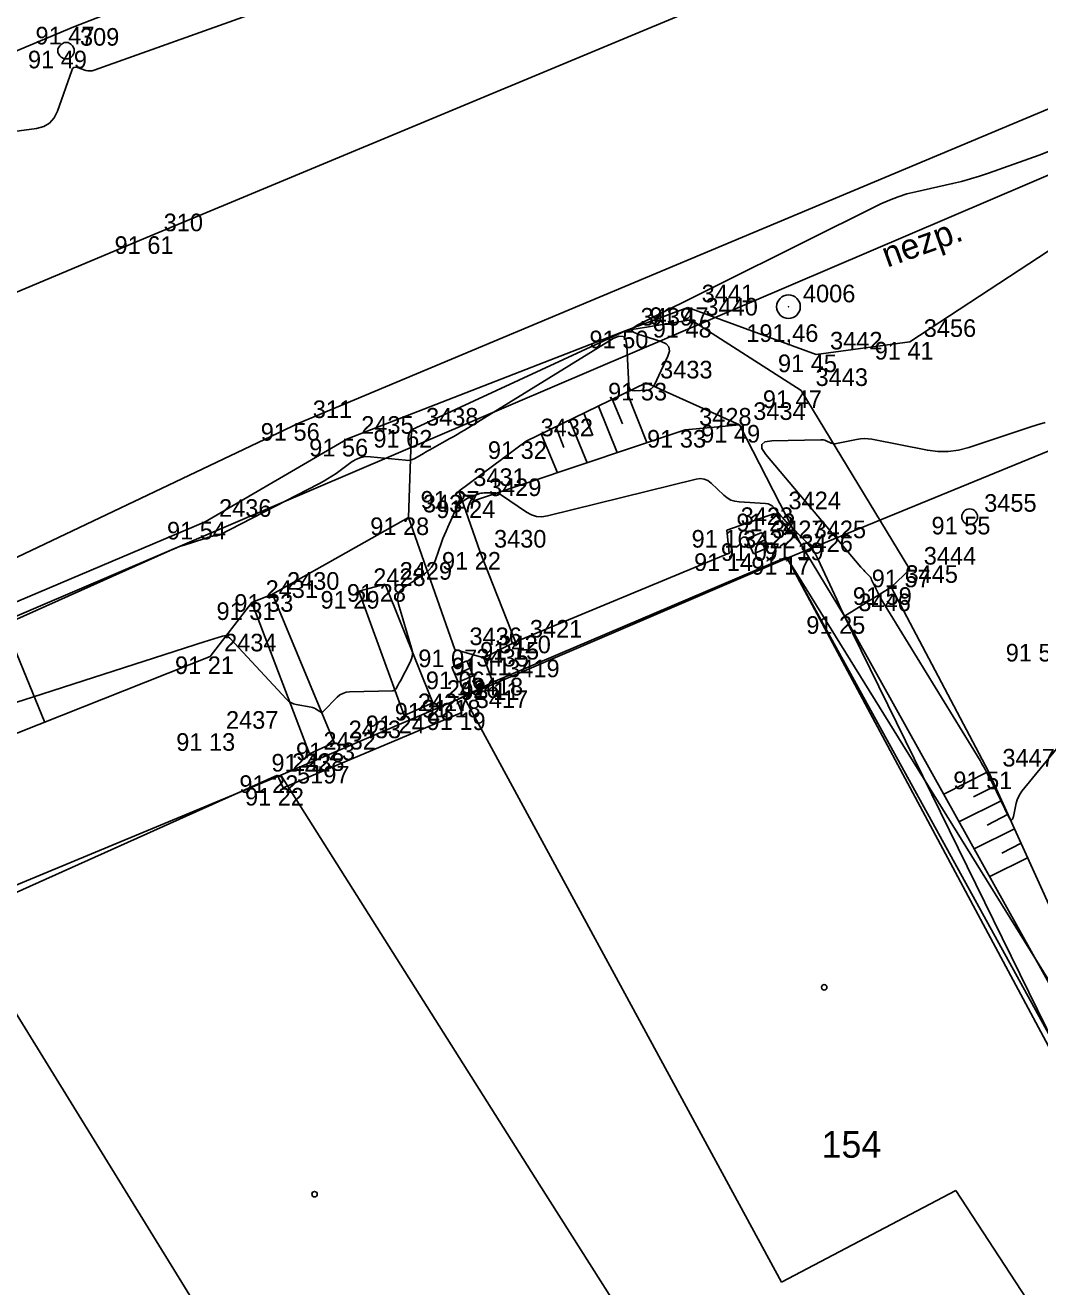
# Model space of a CAD drawing. Extents: x -711081 to -709338, y -1025122 to -1024092.
# Drawn here: x -710543.62 to -710527.5, y -1024855.64 to -1024835.58 of the extents above; entities that cross this region are included whole.
import ezdxf

# ---------------------------------------------------------------- set-up
doc = ezdxf.new("R2010")
doc.units = 0
for name, color, linetype in [('Ex_Minor Contours', 7, 'Continuous'), ('Z_bodove_pole', 7, 'Continuous'), ('Z_bodove_pole_cisla', 7, 'Continuous'), ('Z_bodove_pole_vysky', 7, 'Continuous'), ('Z_body', 7, 'Continuous'), ('Z_body_cisla', 7, 'Continuous'), ('Z_body_vysky_redukovane', 7, 'Continuous'), ('Z_budova', 7, 'Continuous'), ('Z_hrany_paty', 7, 'Continuous'), ('Z_katastr_cisla_stavebni', 7, 'Continuous'), ('Z_katastr_hranice', 7, 'Continuous'), ('Z_katastr_vnitrni_kresba', 7, 'Continuous'), ('Z_katastr_znacky_budov', 7, 'Continuous'), ('Z_komunikace', 7, 'Continuous'), ('Z_komunikace_osa', 7, 'Continuous'), ('Z_patnik_zula', 7, 'Continuous'), ('Z_popisy', 7, 'Continuous'), ('Z_rozhranni', 7, 'Continuous'), ('Z_site_kanalizace_znaky', 7, 'Continuous'), ('Z_site_vodovod_znaky', 7, 'Continuous'), ('Z_srafy_zelen', 7, 'Continuous'), ('Z_technicke_srafy', 7, 'Continuous'), ('Z_vstupy', 7, 'Continuous'), ('Z_zelen_obvod', 7, 'Continuous'), ('Z_zlabek', 7, 'Continuous')]:
    doc.layers.add(name, color=color, linetype=linetype)

# ---------------------------------------------------------------- blocks, each defined once
blk = doc.blocks.new('POINT_DISPLAY')
blk.add_line((0, 0), (0, 0))
blk = doc.blocks.new('Z614')
for p, q in [((-0.13, 0.03), (-0.1, 0.08)), ((-0.13, -0.03), (-0.13, 0.03)), ((-0.1, 0.08), (-0.08, 0.1)), ((-0.08, 0.1), (-0.03, 0.13)), ((-0.03, 0.13), (0.03, 0.13)), ((0.03, 0.13), (0.08, 0.1)), ((0.08, 0.1), (0.1, 0.08)), ((0.1, 0.08), (0.13, 0.03)), ((0.13, 0.03), (0.13, -0.03)), ((-0.1, -0.08), (-0.13, -0.03)), ((-0.08, -0.1), (-0.1, -0.08)), ((-0.03, -0.13), (-0.08, -0.1)), ((0.03, -0.13), (-0.03, -0.13)), ((0.08, -0.1), (0.03, -0.13)), ((0.1, -0.08), (0.08, -0.1)), ((0.13, -0.03), (0.1, -0.08))]:
    blk.add_line(p, q)
blk = doc.blocks.new('Z15')
blk.add_circle((0, 0), 0.125)
blk = doc.blocks.new('Z46260')
for p, q in [((0.13, 0.13), (-0.13, 0.13)), ((-0.13, 0.13), (-0.13, -0.13)), ((0.13, 0), (-0.13, 0)), ((0.13, -0.13), (0.13, 0.13)), ((-0.13, -0.13), (0.13, -0.13))]:
    blk.add_line(p, q)
blk = doc.blocks.new('Z101')
for radius in [0.188, 0.0025]:
    blk.add_circle((0, 0), radius)

msp = doc.modelspace()

# ---------------------------------------------------------------- linework, layer by layer
at = {"layer": 'Ex_Minor Contours'}
for points in [[(-710546.514, -1024837.638), (-710543.441, -1024837.225), (-710543.326, -1024837.195), (-710543.232, -1024837.14), (-710543.159, -1024837.059), (-710543.107, -1024836.953), (-710542.882, -1024836.303), (-710542.868, -1024836.275), (-710542.848, -1024836.258), (-710542.823, -1024836.252), (-710542.792, -1024836.258), (-710542.658, -1024836.302), (-710542.624, -1024836.31), (-710542.591, -1024836.312), (-710542.558, -1024836.309), (-710542.524, -1024836.3), (-710539.776, -1024835.318)], [(-710527.358, -1024837.594), (-710527.506, -1024837.652), (-710528.312, -1024837.938), (-710528.453, -1024837.985), (-710528.595, -1024838.028), (-710528.739, -1024838.067), (-710528.883, -1024838.102), (-710529.464, -1024838.231), (-710529.608, -1024838.267), (-710529.749, -1024838.312), (-710529.887, -1024838.365), (-710530.021, -1024838.427), (-710533.895, -1024840.353), (-710533.96, -1024840.395), (-710533.98, -1024840.433), (-710533.954, -1024840.467), (-710533.883, -1024840.498), (-710533.511, -1024840.613), (-710533.434, -1024840.649), (-710533.391, -1024840.7), (-710533.382, -1024840.766), (-710533.407, -1024840.847), (-710533.618, -1024841.3), (-710533.641, -1024841.336), (-710533.67, -1024841.363), (-710533.706, -1024841.38), (-710533.748, -1024841.388), (-710533.931, -1024841.398), (-710533.972, -1024841.394), (-710534.001, -1024841.379), (-710534.02, -1024841.351), (-710534.027, -1024841.311), (-710534.058, -1024840.681), (-710534.076, -1024840.583), (-710534.118, -1024840.532), (-710534.185, -1024840.526), (-710534.275, -1024840.566), (-710536.637, -1024842.021), (-710536.695, -1024842.056), (-710536.753, -1024842.091), (-710536.811, -1024842.124), (-710536.87, -1024842.157), (-710537.154, -1024842.314), (-710537.188, -1024842.333), (-710537.223, -1024842.353), (-710537.257, -1024842.372), (-710537.292, -1024842.392), (-710537.429, -1024842.471), (-710537.464, -1024842.488), (-710537.5, -1024842.499), (-710537.538, -1024842.504), (-710537.576, -1024842.502), (-710538.133, -1024842.444), (-710538.211, -1024842.443), (-710538.285, -1024842.456), (-710538.355, -1024842.482), (-710538.422, -1024842.522), (-710538.681, -1024842.71), (-710538.746, -1024842.756), (-710538.814, -1024842.799), (-710538.883, -1024842.84), (-710538.953, -1024842.877), (-710540.539, -1024843.69), (-710540.548, -1024843.694), (-710540.557, -1024843.697), (-710540.566, -1024843.699), (-710540.575, -1024843.7), (-710540.613, -1024843.702), (-710540.622, -1024843.702), (-710540.631, -1024843.704), (-710540.64, -1024843.706), (-710540.649, -1024843.708), (-710540.721, -1024843.73), (-710540.75, -1024843.739), (-710540.78, -1024843.749), (-710541.093, -1024843.85), (-710541.15, -1024843.869), (-710541.206, -1024843.889), (-710541.262, -1024843.912), (-710541.317, -1024843.935), (-710548.267, -1024847.049)], [(-710526.884, -1024846.672), (-710527.779, -1024847.761), (-710527.81, -1024847.805), (-710527.836, -1024847.851), (-710527.856, -1024847.9), (-710527.87, -1024847.952), (-710527.916, -1024848.165), (-710527.929, -1024848.206), (-710527.944, -1024848.221), (-710527.964, -1024848.21), (-710527.986, -1024848.174), (-710528.183, -1024847.765), (-710528.203, -1024847.723), (-710528.224, -1024847.682), (-710528.245, -1024847.641), (-710528.267, -1024847.6), (-710528.354, -1024847.437), (-710528.376, -1024847.396), (-710528.399, -1024847.356), (-710528.423, -1024847.316), (-710528.446, -1024847.276), (-710530.015, -1024844.708), (-710530.035, -1024844.675), (-710530.054, -1024844.641), (-710530.072, -1024844.606), (-710530.088, -1024844.571), (-710530.168, -1024844.4), (-710530.178, -1024844.381), (-710530.189, -1024844.362), (-710530.202, -1024844.345), (-710530.217, -1024844.329), (-710530.279, -1024844.267), (-710530.294, -1024844.251), (-710530.309, -1024844.235), (-710530.324, -1024844.218), (-710530.338, -1024844.202), (-710531.852, -1024842.408), (-710531.912, -1024842.315), (-710531.916, -1024842.249), (-710531.864, -1024842.208), (-710531.755, -1024842.192), (-710530.977, -1024842.174), (-710530.955, -1024842.174), (-710530.933, -1024842.177), (-710530.913, -1024842.183), (-710530.892, -1024842.191), (-710530.811, -1024842.227), (-710530.791, -1024842.234), (-710530.77, -1024842.238), (-710530.749, -1024842.239), (-710530.728, -1024842.236), (-710530.407, -1024842.169), (-710530.346, -1024842.159), (-710530.285, -1024842.156), (-710530.224, -1024842.159), (-710530.163, -1024842.168), (-710529.283, -1024842.341), (-710529.117, -1024842.363), (-710528.952, -1024842.364), (-710528.789, -1024842.342), (-710528.626, -1024842.299), (-710527.655, -1024841.975), (-710527.535, -1024841.937), (-710527.413, -1024841.901)], [(-710527.253, -1024851.809), (-710530.471, -1024845.243), (-710530.535, -1024845.111), (-710530.599, -1024844.979), (-710530.661, -1024844.847), (-710530.723, -1024844.714), (-710531.023, -1024844.067), (-710531.061, -1024843.994), (-710531.104, -1024843.925), (-710531.154, -1024843.86), (-710531.209, -1024843.799), (-710531.502, -1024843.503), (-710531.531, -1024843.474), (-710531.559, -1024843.444), (-710531.586, -1024843.413), (-710531.613, -1024843.382), (-710531.719, -1024843.256), (-710531.748, -1024843.228), (-710531.779, -1024843.208), (-710531.815, -1024843.194), (-710531.854, -1024843.188), (-710532.276, -1024843.163), (-710532.343, -1024843.153), (-710532.406, -1024843.133), (-710532.464, -1024843.101), (-710532.516, -1024843.058), (-710532.718, -1024842.865), (-710532.771, -1024842.825), (-710532.828, -1024842.801), (-710532.889, -1024842.793), (-710532.955, -1024842.802), (-710535.322, -1024843.387), (-710535.41, -1024843.4), (-710535.494, -1024843.394), (-710535.575, -1024843.37), (-710535.653, -1024843.327), (-710536.052, -1024843.054), (-710536.081, -1024843.037), (-710536.111, -1024843.026), (-710536.142, -1024843.019), (-710536.175, -1024843.017), (-710536.328, -1024843.021), (-710536.353, -1024843.023), (-710536.377, -1024843.026), (-710536.401, -1024843.032), (-710536.424, -1024843.039), (-710536.517, -1024843.073), (-710536.54, -1024843.082), (-710536.562, -1024843.093), (-710536.584, -1024843.104), (-710536.605, -1024843.117), (-710536.698, -1024843.178), (-710536.719, -1024843.194), (-710536.737, -1024843.212), (-710536.752, -1024843.233), (-710536.765, -1024843.256), (-710536.906, -1024843.566), (-710536.932, -1024843.626), (-710536.957, -1024843.686), (-710536.981, -1024843.747), (-710537.003, -1024843.809), (-710537.099, -1024844.083), (-710537.126, -1024844.145), (-710537.162, -1024844.202), (-710537.207, -1024844.251), (-710537.261, -1024844.294), (-710537.592, -1024844.518), (-710537.654, -1024844.573), (-710537.691, -1024844.636), (-710537.703, -1024844.709), (-710537.689, -1024844.791), (-710537.479, -1024845.486), (-710537.468, -1024845.545), (-710537.467, -1024845.602), (-710537.479, -1024845.658), (-710537.502, -1024845.712), (-710537.658, -1024846.006), (-710537.675, -1024846.037), (-710537.692, -1024846.069), (-710537.727, -1024846.132), (-710537.737, -1024846.146), (-710537.749, -1024846.156), (-710537.763, -1024846.163), (-710537.78, -1024846.165), (-710538.464, -1024846.184), (-710538.52, -1024846.19), (-710538.571, -1024846.207), (-710538.619, -1024846.233), (-710538.662, -1024846.27), (-710538.878, -1024846.49), (-710538.893, -1024846.501), (-710538.907, -1024846.506), (-710538.923, -1024846.504), (-710538.939, -1024846.497), (-710539.005, -1024846.454), (-710539.021, -1024846.444), (-710539.039, -1024846.436), (-710539.057, -1024846.43), (-710539.076, -1024846.426), (-710539.314, -1024846.383), (-710539.359, -1024846.372), (-710539.4, -1024846.354), (-710539.437, -1024846.329), (-710539.47, -1024846.298), (-710540.367, -1024845.329), (-710540.393, -1024845.307), (-710540.421, -1024845.294), (-710540.451, -1024845.291), (-710540.484, -1024845.297), (-710540.621, -1024845.339), (-710540.655, -1024845.35), (-710540.69, -1024845.361), (-710540.724, -1024845.372), (-710540.758, -1024845.383), (-710543.506, -1024846.266), (-710543.754, -1024846.349)]]:
    msp.add_lwpolyline(points, dxfattribs=at)
at = {"layer": 'Z_budova'}
for p, q in [((-710536.19, -1024846.03), (-710531.52, -1024844.04)), ((-710531.52, -1024844.04), (-710526.72, -1024852.78)), ((-710536.76, -1024846.31), (-710536.19, -1024846.03)), ((-710536.68, -1024846.51), (-710536.76, -1024846.31)), ((-710539.61, -1024847.51), (-710544.72, -1024849.8)), ((-710539.52, -1024847.71), (-710539.61, -1024847.51))]:
    msp.add_line(p, q, dxfattribs=at)
at = {"layer": 'Z_hrany_paty'}
for p, q in [((-710533.13, -1024842.02), (-710536.48, -1024843.14)), ((-710533.13, -1024842.02), (-710532.27, -1024841.94)), ((-710536.73, -1024842.99), (-710536.48, -1024843.14)), ((-710539.69, -1024844.63), (-710537.53, -1024843.41)), ((-710529.86, -1024844.52), (-710528.31, -1024847.45)), ((-710540.68, -1024845.62), (-710540.02, -1024844.76)), ((-710540.68, -1024845.62), (-710545.01, -1024847.34)), ((-710528.31, -1024847.45), (-710526.08, -1024852.38))]:
    msp.add_line(p, q, dxfattribs=at)
at = {"layer": 'Z_katastr_hranice'}
for p, q in [((-710562.9, -1024853.16), (-710522.93, -1024836.07)), ((-710531.51, -1024844.06), (-710526.89, -1024842.16)), ((-710531.51, -1024844.06), (-710536.65, -1024846.26)), ((-710521.2, -1024860.71), (-710531.51, -1024844.06)), ((-710536.65, -1024846.26), (-710539.56, -1024847.51)), ((-710539.56, -1024847.51), (-710544.77, -1024849.67)), ((-710539.56, -1024847.51), (-710535.45, -1024854.01)), ((-710535.45, -1024854.01), (-710530.21, -1024862.29))]:
    msp.add_line(p, q, dxfattribs=at)
at = {"layer": 'Z_katastr_vnitrni_kresba'}
for p, q in [((-710526.72, -1024853.01), (-710531.51, -1024844.06)), ((-710536.65, -1024846.26), (-710531.6, -1024855.57)), ((-710544.77, -1024849.67), (-710540.21, -1024857.07)), ((-710531.6, -1024855.57), (-710528.83, -1024854.11)), ((-710528.83, -1024854.11), (-710523.54, -1024862.2))]:
    msp.add_line(p, q, dxfattribs=at)
at = {"layer": 'Z_katastr_znacky_budov'}
for centre in [(-710530.922, -1024850.88), (-710539.022, -1024854.17)]:
    msp.add_circle(centre, 0.0437, dxfattribs=at)
at = {"layer": 'Z_komunikace'}
for p, q in [((-710542.85, -1024835.61), (-710529.22, -1024830.3)), ((-710556.39, -1024841.31), (-710542.85, -1024835.61)), ((-710539.27, -1024841.91), (-710526.42, -1024836.52)), ((-710544.51, -1024844.4), (-710539.27, -1024841.91))]:
    msp.add_line(p, q, dxfattribs=at)
at = {"layer": 'Z_komunikace_osa'}
for p, q in [((-710541.64, -1024838.94), (-710528.14, -1024833.31)), ((-710555.08, -1024844.58), (-710541.64, -1024838.94))]:
    msp.add_line(p, q, dxfattribs=at)
at = {"layer": 'Z_rozhranni'}
for p, q in [((-710529.56, -1024840.62), (-710525.29, -1024837.81)), ((-710534.07, -1024840.44), (-710533.09, -1024840.07)), ((-710533.09, -1024840.07), (-710531.05, -1024840.82)), ((-710538.5, -1024842.16), (-710534.07, -1024840.44)), ((-710531.05, -1024840.82), (-710529.56, -1024840.62)), ((-710538.5, -1024842.16), (-710540.76, -1024843.48)), ((-710532.47, -1024843.61), (-710531.71, -1024843.35)), ((-710531.71, -1024843.35), (-710531.31, -1024843.81)), ((-710540.76, -1024843.48), (-710549.21, -1024847.06)), ((-710532.43, -1024843.98), (-710532.47, -1024843.61)), ((-710535.83, -1024845.39), (-710532.43, -1024843.98)), ((-710539.69, -1024844.63), (-710540.02, -1024844.76)), ((-710539.69, -1024844.63), (-710538.71, -1024846.99)), ((-710538.32, -1024844.58), (-710537.9, -1024844.47)), ((-710537.6, -1024846.56), (-710538.32, -1024844.58)), ((-710537.9, -1024844.47), (-710537.14, -1024846.36)), ((-710540.02, -1024844.76), (-710539.1, -1024847.17)), ((-710536.33, -1024845.64), (-710535.83, -1024845.39)), ((-710536.33, -1024845.64), (-710536.19, -1024846.03)), ((-710537.14, -1024846.36), (-710537.6, -1024846.56)), ((-710539.1, -1024847.17), (-710538.71, -1024846.99))]:
    msp.add_line(p, q, dxfattribs=at)
at = {"layer": 'Z_srafy_zelen'}
msp.add_line((-710529.86, -1024844.52), (-710530.6, -1024844.98), dxfattribs=at)
at = {"layer": 'Z_technicke_srafy'}
for p, q in [((-710534.06, -1024841.42), (-710533.74, -1024842.22)), ((-710534.51, -1024841.64), (-710534.21, -1024842.38)), ((-710534.29, -1024841.53), (-710534.13, -1024841.92)), ((-710534.74, -1024841.75), (-710534.6, -1024842.11)), ((-710535.19, -1024841.97), (-710535.06, -1024842.3)), ((-710534.97, -1024841.86), (-710534.69, -1024842.54)), ((-710535.42, -1024842.08), (-710535.16, -1024842.7)), ((-710544.05, -1024844.87), (-710543.31, -1024846.67)), ((-710528.31, -1024847.45), (-710529.02, -1024847.81)), ((-710528.21, -1024847.68), (-710528.55, -1024847.85)), ((-710528.1, -1024847.91), (-710528.78, -1024848.25)), ((-710528, -1024848.13), (-710528.33, -1024848.3)), ((-710527.9, -1024848.36), (-710528.54, -1024848.68)), ((-710527.79, -1024848.59), (-710528.1, -1024848.75)), ((-710527.69, -1024848.82), (-710528.29, -1024849.12))]:
    msp.add_line(p, q, dxfattribs=at)
at = {"layer": 'Z_vstupy'}
msp.add_line((-710539.52, -1024847.71), (-710536.68, -1024846.51), dxfattribs=at)
at = {"layer": 'Z_zelen_obvod'}
for p, q in [((-710534.07, -1024840.44), (-710533.04, -1024840.27)), ((-710533.04, -1024840.27), (-710531.29, -1024841.39)), ((-710537.48, -1024842.02), (-710534.07, -1024840.44)), ((-710535.66, -1024842.2), (-710533.75, -1024841.27)), ((-710533.75, -1024841.27), (-710532.27, -1024841.94)), ((-710531.29, -1024841.39), (-710529.56, -1024844.24)), ((-710537.53, -1024843.41), (-710537.48, -1024842.02)), ((-710532.27, -1024841.94), (-710531.31, -1024843.81)), ((-710536.73, -1024842.99), (-710535.66, -1024842.2)), ((-710536.39, -1024843.96), (-710536.73, -1024842.99)), ((-710536.79, -1024845.51), (-710537.53, -1024843.41)), ((-710536.39, -1024843.96), (-710535.83, -1024845.39)), ((-710529.56, -1024844.24), (-710529.86, -1024844.52)), ((-710536.79, -1024845.51), (-710536.33, -1024845.64))]:
    msp.add_line(p, q, dxfattribs=at)
at = {"layer": 'Z_zlabek'}
for p, q in [((-710531.31, -1024843.81), (-710530.6, -1024844.98)), ((-710530.6, -1024844.98), (-710526.39, -1024852.54))]:
    msp.add_line(p, q, dxfattribs=at)

# ---------------------------------------------------------------- block references
at = {"layer": 'Z_bodove_pole'}
msp.add_blockref('Z101', (-710531.49, -1024840.06), dxfattribs=at)
at = {"layer": 'Z_body'}
for p in [(-710542.85, -1024835.61), (-710542.97, -1024835.99), (-710541.64, -1024838.94), (-710533.09, -1024840.07), (-710531.49, -1024840.06), (-710533.04, -1024840.27), (-710534.07, -1024840.44), (-710529.56, -1024840.62), (-710531.05, -1024840.82), (-710533.75, -1024841.27), (-710531.29, -1024841.39), (-710539.27, -1024841.91), (-710537.48, -1024842.02), (-710533.13, -1024842.02), (-710532.27, -1024841.94), (-710538.5, -1024842.16), (-710535.66, -1024842.2), (-710536.73, -1024842.99), (-710536.48, -1024843.14), (-710537.53, -1024843.41), (-710531.71, -1024843.35), (-710528.61, -1024843.4), (-710540.76, -1024843.48), (-710532.47, -1024843.61), (-710531.98, -1024843.82), (-710531.31, -1024843.81), (-710536.39, -1024843.96), (-710532.43, -1024843.98), (-710531.52, -1024844.04), (-710529.56, -1024844.24), (-710539.69, -1024844.63), (-710538.32, -1024844.58), (-710537.9, -1024844.47), (-710529.86, -1024844.52), (-710540.02, -1024844.76), (-710530.6, -1024844.98), (-710535.83, -1024845.39), (-710540.68, -1024845.62), (-710536.79, -1024845.51), (-710536.33, -1024845.64), (-710536.67, -1024845.86), (-710536.19, -1024846.03), (-710537.14, -1024846.36), (-710536.76, -1024846.31), (-710537.6, -1024846.56), (-710536.68, -1024846.51), (-710540.66, -1024846.84), (-710538.71, -1024846.99), (-710539.1, -1024847.17), (-710528.31, -1024847.45), (-710539.61, -1024847.51), (-710539.52, -1024847.71)]:
    msp.add_blockref('POINT_DISPLAY', p, dxfattribs=at)
at = {"layer": 'Z_patnik_zula'}
msp.add_blockref('Z15', (-710528.61, -1024843.4), dxfattribs=at)
at = {"layer": 'Z_site_kanalizace_znaky', "rotation": 23.399999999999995}
for p in [(-710531.98, -1024843.82), (-710536.67, -1024845.86)]:
    msp.add_blockref('Z46260', p, dxfattribs=at)
at = {"layer": 'Z_site_vodovod_znaky'}
msp.add_blockref('Z614', (-710542.97, -1024835.99), dxfattribs=at)

# ---------------------------------------------------------------- texts
at = {"layer": 'Z_bodove_pole_cisla'}
msp.add_text('4006', height=0.28, dxfattribs=at).set_placement((-710531.26, -1024839.99))
at = {"layer": 'Z_bodove_pole_vysky'}
msp.add_text('191,46', height=0.28, dxfattribs=at).set_placement((-710532.16, -1024840.62))
at = {"layer": 'Z_body_cisla'}
for s, p in [('309', (-710542.75, -1024835.91)), ('310', (-710541.42, -1024838.86)), ('3441', (-710532.87, -1024839.99)), ('3440', (-710532.81, -1024840.2)), ('3439', (-710533.84, -1024840.36)), ('3456', (-710529.34, -1024840.54)), ('3442', (-710530.83, -1024840.74)), ('3433', (-710533.53, -1024841.2)), ('3443', (-710531.06, -1024841.32)), ('311', (-710539.05, -1024841.83)), ('3434', (-710532.05, -1024841.86)), ('2435', (-710538.28, -1024842.08)), ('3438', (-710537.25, -1024841.95)), ('3432', (-710535.43, -1024842.12)), ('3428', (-710532.91, -1024841.95)), ('3431', (-710536.5, -1024842.91)), ('3429', (-710536.25, -1024843.07)), ('3424', (-710531.49, -1024843.28)), ('3455', (-710528.38, -1024843.32)), ('2436', (-710540.54, -1024843.4)), ('3437', (-710537.3, -1024843.33)), ('3423', (-710532.25, -1024843.53)), ('3430', (-710536.17, -1024843.89)), ('3422', (-710532.21, -1024843.9)), ('3427', (-710531.75, -1024843.74)), ('3425', (-710531.09, -1024843.74)), ('3426', (-710531.3, -1024843.96)), ('3444', (-710529.34, -1024844.16)), ('2428', (-710538.09, -1024844.5)), ('2429', (-710537.67, -1024844.4)), ('3445', (-710529.63, -1024844.45)), ('2431', (-710539.8, -1024844.69)), ('2430', (-710539.46, -1024844.56)), ('3446', (-710530.38, -1024844.9)), ('3421', (-710535.6, -1024845.32)), ('3436', (-710536.56, -1024845.44)), ('2434', (-710540.46, -1024845.54)), ('3420', (-710536.1, -1024845.57)), ('3435', (-710536.45, -1024845.78)), ('3419', (-710535.96, -1024845.95)), ('2426', (-710536.92, -1024846.28)), ('3418', (-710536.54, -1024846.24)), ('2427', (-710537.38, -1024846.49)), ('3417', (-710536.46, -1024846.44)), ('2437', (-710540.43, -1024846.77)), ('2433', (-710538.48, -1024846.92)), ('2432', (-710538.88, -1024847.1)), ('2438', (-710539.38, -1024847.44)), ('3447', (-710528.09, -1024847.37)), ('5197', (-710539.3, -1024847.64))]:
    msp.add_text(s, height=0.28, dxfattribs=at).set_placement(p)
at = {"layer": 'Z_body_vysky_redukovane'}
for s, p in [('91 47', (-710543.457, -1024835.89)), ('91 49', (-710543.577, -1024836.27)), ('91 61', (-710542.2, -1024839.22)), ('91 47', (-710533.697, -1024840.35)), ('91 50', (-710534.653, -1024840.72)), ('91 48', (-710533.647, -1024840.55)), ('91 41', (-710530.12, -1024840.9)), ('91 45', (-710531.657, -1024841.1)), ('91 53', (-710534.357, -1024841.55)), ('91 47', (-710531.897, -1024841.67)), ('91 56', (-710539.877, -1024842.19)), ('91 62', (-710538.087, -1024842.3)), ('91 33', (-710533.737, -1024842.3)), ('91 49', (-710532.877, -1024842.22)), ('91 56', (-710539.107, -1024842.44)), ('91 32', (-710536.267, -1024842.48)), ('91 27', (-710537.337, -1024843.27)), ('91 24', (-710537.087, -1024843.42)), ('91 28', (-710538.137, -1024843.69)), ('91 22', (-710532.317, -1024843.63)), ('91 55', (-710529.217, -1024843.68)), ('91 54', (-710541.367, -1024843.76)), ('91 16', (-710533.03, -1024843.89)), ('91 07', (-710532.563, -1024844.1)), ('91 19', (-710531.87, -1024844.09)), ('91 22', (-710536.997, -1024844.24)), ('91 14', (-710532.99, -1024844.26)), ('91 17', (-710532.08, -1024844.32)), ('91 57', (-710530.167, -1024844.52)), ('91 33', (-710540.297, -1024844.91)), ('91 29', (-710538.927, -1024844.86)), ('91 28', (-710538.507, -1024844.75)), ('91 59', (-710530.467, -1024844.8)), ('91 31', (-710540.58, -1024845.04)), ('91 25', (-710531.207, -1024845.26)), ('91 15', (-710536.39, -1024845.67)), ('91 52', (-710528.037, -1024845.7)), ('91 21', (-710541.24, -1024845.9)), ('91 07', (-710537.373, -1024845.79)), ('91 11', (-710536.843, -1024845.92)), ('91 06', (-710537.253, -1024846.14)), ('91 11', (-710536.703, -1024846.31)), ('91 23', (-710537.747, -1024846.64)), ('91 18', (-710537.32, -1024846.59)), ('91 24', (-710538.207, -1024846.84)), ('91 19', (-710537.24, -1024846.79)), ('91 13', (-710541.22, -1024847.12)), ('91 23', (-710539.317, -1024847.27)), ('91 22', (-710539.707, -1024847.45)), ('91 51', (-710528.87, -1024847.73)), ('91 22', (-710540.217, -1024847.79)), ('91 22', (-710540.127, -1024847.99))]:
    msp.add_text(s, height=0.28, dxfattribs=at).set_placement(p)
at = {"layer": 'Z_katastr_cisla_stavebni'}
msp.add_text('154', height=0.425, dxfattribs=at).set_placement((-710530.964, -1024853.59))
at = {"layer": 'Z_popisy'}
msp.add_text('nezp.', height=0.4, rotation=19.8, dxfattribs=at).set_placement((-710529.92, -1024839.44))

doc.saveas('drawing.dxf')
